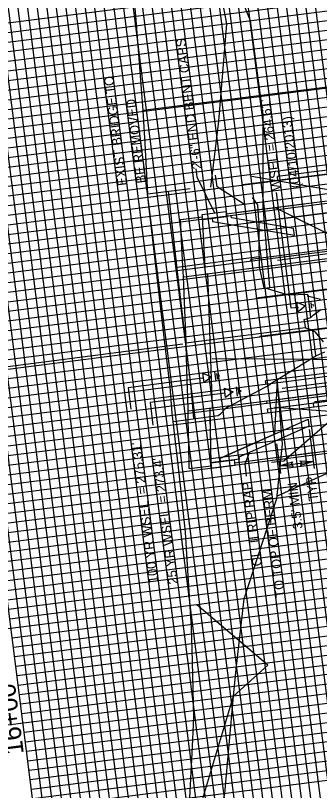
# Model space of a CAD drawing. Extents: x 2166991 to 2168413, y 842679 to 844296.
# Drawn here: x 2167677.7 to 2167837.4, y 843150.5 to 843556.7 of the extents above; entities that cross this region are included whole.
import ezdxf

# ---------------------------------------------------------------- set-up
doc = ezdxf.new("R2010")
doc.units = 0
for name, color, linetype in [('Exist Drainage Structure Bridge Floor', 7, 'Continuous'), ('Exist Horizontal Alignment', 7, 'Continuous'), ('Exist Hydrographic Natural Ground Left', 7, 'Continuous'), ('Exist Hydrographic Natural Ground Right', 7, 'Continuous'), ('Exist Vertical Profile Ground Line', 7, 'Continuous'), ('Old_Level_46', 7, 'Continuous'), ('Prop Drainage Structure Bridge', 7, 'Continuous'), ('Prop Erosion Rip Rap Class II', 7, 'Continuous'), ('Prop Hydrographic Scour Overtopping', 7, 'Continuous'), ('Prop Plan Preparation Drainage Notes Label', 7, 'Continuous'), ('Prop Plan Preparation Excavation Hatching', 7, 'Continuous'), ('Prop Plan Preparation Sheet Bridge Report Limited Study CELL', 7, 'Continuous'), ('Prop Plan Preparation Station Label', 7, 'Continuous'), ('Prop Plan Preparation Stream Water Surface', 7, 'Continuous'), ('Prop Plan Preparation Water Surface Symbol CELL', 7, 'Continuous'), ('Scratch_Level_2', 7, 'Continuous'), ('Scratch_Level_3', 7, 'Continuous'), ('Scratch_Level_4', 7, 'Continuous'), ('Scratch_Level_8', 7, 'Continuous')]:
    doc.layers.add(name, color=color, linetype=linetype)

msp = doc.modelspace()

# ---------------------------------------------------------------- linework, layer by layer
at = {"layer": 'Exist Drainage Structure Bridge Floor'}
for p, q in [((2167747.12, 843463.2), (2167769.41, 843466.04)), ((2167762.53, 843424.84), (2167805.8, 843430.37)), ((2167767.21, 843385.11), (2167830.11, 843393.15)), ((2167760.56, 843343.94), (2167784.24, 843346.96))]:
    msp.add_line(p, q, dxfattribs=at)
for points in [[(2167760.56, 843343.94), (2167760.1, 843348.27), (2167758.9, 843362.01), (2167756.48, 843382.13), (2167751.73, 843422.48), (2167747.12, 843463.2)], [(2167771.47, 843345.33), (2167771.01, 843349.66), (2167769.81, 843363.4), (2167767.4, 843383.52), (2167762.64, 843423.88), (2167758.03, 843464.59)]]:
    msp.add_lwpolyline(points, dxfattribs=at)
at = {"layer": 'Exist Horizontal Alignment'}
for points in [[(2167698.15, 843912.6), (2167700.9, 843897.02), (2167704.98, 843873.76), (2167712.78, 843830.82), (2167715.25, 843815.08), (2167719.44, 843788.58), (2167721.24, 843770.88), (2167724.14, 843742.72), (2167725.44, 843727.75), (2167727.98, 843698.45), (2167729.76, 843678.17), (2167732.36, 843648.31), (2167734.01, 843631.06), (2167736.91, 843601.24), (2167740.82, 843556.48), (2167742.38, 843536.39), (2167744.64, 843506.82), (2167745.73, 843489.59), (2167747.12, 843463.2)], [(2167751.39, 842824.91), (2167752.39, 842844.74), (2167753.95, 842874.72), (2167755.15, 842897.27), (2167757.06, 842927.31), (2167757.92, 842945.41), (2167760.09, 842975.47), (2167761.25, 842993.97), (2167762.76, 843023.98), (2167763.76, 843044.55), (2167765.23, 843074.51), (2167766.29, 843095.78), (2167768.15, 843125.8), (2167769.02, 843139.96), (2167770.48, 843169.95), (2167771.39, 843188.46), (2167770.67, 843218.15), (2167770.25, 843236.07), (2167768.33, 843265.68), (2167767.02, 843285.86), (2167763.97, 843315.19), (2167760.56, 843343.94)]]:
    msp.add_lwpolyline(points, dxfattribs=at)
at = {"layer": 'Exist Hydrographic Natural Ground Left'}
for points in [[(2167811.3, 843414.12), (2167807.83, 843456.76), (2167807.84, 843504.28), (2167801.18, 843553.83), (2167790.23, 843580.86), (2167790.98, 843602.94), (2167784.08, 843652.46), (2167781.01, 843702.48), (2167748.47, 843748.73), (2167729.16, 843847.07), (2167716.86, 843895.91), (2167712.99, 843945.82), (2167712.65, 843970.98), (2167709.18, 843995.74)], [(2167757.79, 842963.56), (2167770.55, 842995.45), (2167773.98, 843046.3), (2167776.61, 843068.3), (2167777.35, 843097.13), (2167787.62, 843148.85), (2167792.18, 843199.84), (2167793.61, 843214.01), (2167797.76, 843250.96), (2167815.06, 843303.58), (2167817.99, 843332.01), (2167815.17, 843366.59)]]:
    msp.add_lwpolyline(points, dxfattribs=at)
at = {"layer": 'Exist Hydrographic Natural Ground Right'}
for points in [[(2167780.31, 843466.62), (2167784.52, 843501.3), (2167788.71, 843552.24), (2167783.57, 843580.01), (2167779.35, 843601.45), (2167769.15, 843650.56), (2167754.8, 843699.13), (2167753.25, 843749.34), (2167741.46, 843798.24), (2167722.31, 843846.2), (2167712.49, 843895.35), (2167692.49, 843943.2), (2167687.3, 843967.74), (2167682.51, 843992.33)], [(2167764.31, 843094.3), (2167776.57, 843147.44), (2167792.18, 843199.84), (2167810.26, 843216.13), (2167772.9, 843247.78)]]:
    msp.add_lwpolyline(points, dxfattribs=at)
at = {"layer": 'Exist Vertical Profile Ground Line'}
for points in [[(2167805.68, 843446.76), (2167804.98, 843457.45), (2167802.15, 843461.2)], [(2167837.93, 843407.87), (2167831.79, 843409.39), (2167831.14, 843410.52), (2167821.21, 843410.07), (2167808.38, 843413.88), (2167805.82, 843424.85), (2167805.79, 843436.55), (2167805.78, 843445.31), (2167805.69, 843446.57)], [(2167839.45, 843385.69), (2167835.28, 843390.74), (2167832.96, 843391.91), (2167830.17, 843392.87), (2167829.29, 843397.37), (2167832.89, 843398.38), (2167834.04, 843399.62), (2167838.15, 843402.55)], [(2167784.24, 843346.96), (2167785.37, 843347.8), (2167788.65, 843351.29), (2167790.08, 843351.91), (2167811.52, 843363.23), (2167811.76, 843363.73), (2167835.45, 843378.32), (2167840.17, 843380.47)]]:
    msp.add_lwpolyline(points, dxfattribs=at)
at = {"layer": 'Old_Level_46'}
for points in [[(2167798.06, 843457.66), (2167783.65, 843466.84), (2167782.87, 843472.96)], [(2167775.92, 843366.58), (2167736.94, 843361.6), (2167738.37, 843350.34)], [(2167787.78, 843358.8), (2167748.42, 843353.78), (2167749.94, 843341.89)]]:
    msp.add_lwpolyline(points, dxfattribs=at)
at = {"layer": 'Prop Drainage Structure Bridge'}
for p, q in [((2167788.33, 843452.77), (2167829.5, 843458.03)), ((2167794.54, 843453.55), (2167848.25, 843460.41)), ((2167775.78, 843452.41), (2167788.18, 843454)), ((2167788.17, 843454), (2167788.52, 843451.28)), ((2167764.37, 843449.7), (2167775.94, 843451.17)), ((2167766.02, 843449.91), (2167775.94, 843451.17)), ((2167776.13, 843449.69), (2167788.53, 843451.27)), ((2167765.91, 843419.65), (2167960.44, 843444.5)), ((2167768.38, 843349.4), (2167969.63, 843375.1)), ((2167821.41, 843325.93), (2167864.73, 843331.46)), ((2167780.32, 843322.19), (2167792.72, 843323.77)), ((2167793.05, 843321.04), (2167792.71, 843323.76)), ((2167792.9, 843322.27), (2167834.07, 843327.53)), ((2167768.96, 843319.23), (2167780.51, 843320.7)), ((2167770.59, 843319.44), (2167780.51, 843320.7)), ((2167780.67, 843319.46), (2167793.07, 843321.05))]:
    msp.add_line(p, q, dxfattribs=at)
for points in [[(2167768.96, 843319.23), (2167768.73, 843332.94), (2167768.63, 843337.97), (2167768.48, 843344.95), (2167768.38, 843349.4), (2167768.21, 843356.31), (2167767.95, 843365.56), (2167767.37, 843383.75), (2167767.32, 843385.13), (2167766.83, 843398.23), (2167765.91, 843419.65), (2167765.64, 843425.24), (2167764.98, 843438.32), (2167764.72, 843443.32), (2167764.37, 843449.7)], [(2167780.51, 843320.7), (2167779.93, 843350.87), (2167781.17, 843351.03), (2167778.7, 843421.28), (2167777.46, 843421.13), (2167775.94, 843451.17)]]:
    msp.add_lwpolyline(points, dxfattribs=at)
at = {"layer": 'Prop Erosion Rip Rap Class II'}
for points in [[(2167781.08, 843450.32), (2167781.28, 843448.75), (2167824.28, 843441.49), (2167823.72, 843445.01), (2167791.15, 843450.59), (2167790.99, 843451.61), (2167788.51, 843451.29)], [(2167785.27, 843322.82), (2167785.06, 843324.39), (2167831.4, 843345.02), (2167831.8, 843341.39), (2167814.14, 843333.63), (2167795.08, 843325.09), (2167795.19, 843324.06), (2167792.71, 843323.75)]]:
    msp.add_lwpolyline(points, close=True, dxfattribs=at)
at = {"layer": 'Prop Hydrographic Scour Overtopping'}
for p, q in [((2167960.44, 843444.56), (2167801.84, 843472.35)), ((2167969.56, 843375.09), (2167815.18, 843304.73)), ((2167814.98, 843365.72), (2167814.45, 843369.88))]:
    msp.add_line(p, q, dxfattribs=at)
at = {"layer": 'Prop Plan Preparation Drainage Notes Label'}
for p, q in [((2167765.56, 843384.32), (2167521.8, 843353.19)), ((2167832.06, 843339.76), (2167834.67, 843319.3)), ((2167814.9, 843332.2), (2167816.89, 843316.6)), ((2167816.37, 843320.64), (2167834.21, 843322.92)), ((2167823.97, 843296.65), (2167823.97, 843296.58))]:
    msp.add_line(p, q, dxfattribs=at)
for points in [[(2167772.38, 843476.34), (2167772.93, 843472.04), (2167782.2, 843453.23)], [(2167814.63, 843463.88), (2167822.41, 843403.37), (2167826.31, 843403.86)], [(2167895.15, 843315.83), (2167893.14, 843331.53), (2167887.44, 843375.99), (2167781.12, 843376.66)], [(2167854.04, 843318.38), (2167850.29, 843348.53), (2167813.82, 843351.12)], [(2167799.13, 843315.18), (2167798.3, 843321.71), (2167800.64, 843327.58)]]:
    msp.add_lwpolyline(points, dxfattribs=at)
for points in [[(2167823.5, 843320.33), (2167816.37, 843320.64), (2167823.23, 843322.78), (2167822.49, 843321.42)], [(2167827.08, 843323.23), (2167834.21, 843322.92), (2167827.35, 843320.79), (2167828.09, 843322.14)]]:
    msp.add_lwpolyline(points, close=True, dxfattribs=at)
at = {"layer": 'Prop Plan Preparation Excavation Hatching'}
for p, q in [((2167776.13, 843449.7), (2167775.78, 843452.43)), ((2167780.32, 843322.17), (2167780.67, 843319.45))]:
    msp.add_line(p, q, dxfattribs=at)
msp.add_lwpolyline([(2167780.51, 843322.21), (2167780.02, 843346.42), (2167784.24, 843346.96), (2167785.37, 843347.8), (2167788.65, 843351.29), (2167790.08, 843351.91), (2167811.52, 843363.23), (2167811.76, 843363.73), (2167815.13, 843365.81), (2167813.8, 843337.17), (2167785.06, 843324.39), (2167785.27, 843322.82), (2167781.42, 843322.33)], close=True, dxfattribs=at)
at = {"layer": 'Prop Plan Preparation Sheet Bridge Report Limited Study CELL'}
for p, q in [((2167933.95, 842789.5), (2167775.57, 844029.42)), ((2167884.35, 842783.16), (2167725.98, 844023.09)), ((2167834.76, 842776.83), (2167676.38, 844016.75)), ((2167785.16, 842770.49), (2167626.78, 844010.42)), ((2167735.56, 842764.16), (2167577.19, 844004.08)), ((2167910.94, 842811.76), (2167758.9, 844002.09)), ((2167915.9, 842812.39), (2167763.86, 844002.72)), ((2167920.86, 842813.03), (2167768.82, 844003.36)), ((2167925.82, 842813.66), (2167773.78, 844003.99)), ((2167886.15, 842808.59), (2167734.11, 843998.92)), ((2167891.11, 842809.23), (2167739.06, 843999.56)), ((2167896.07, 842809.86), (2167744.02, 844000.19)), ((2167901.03, 842810.49), (2167748.98, 844000.82)), ((2167905.98, 842811.13), (2167753.94, 844001.46)), ((2167851.43, 842804.16), (2167699.39, 843994.49)), ((2167856.39, 842804.79), (2167704.35, 843995.12)), ((2167861.35, 842805.43), (2167709.31, 843995.76)), ((2167866.31, 842806.06), (2167714.27, 843996.39)), ((2167871.27, 842806.69), (2167719.23, 843997.02)), ((2167876.23, 842807.33), (2167724.19, 843997.66)), ((2167816.71, 842799.72), (2167664.67, 843990.05)), ((2167821.67, 842800.36), (2167669.63, 843990.69)), ((2167826.63, 842800.99), (2167674.59, 843991.32)), ((2167836.55, 842802.26), (2167684.51, 843992.59)), ((2167841.51, 842802.89), (2167689.47, 843993.22)), ((2167846.47, 842803.53), (2167694.43, 843993.85)), ((2167786.95, 842795.92), (2167634.91, 843986.25)), ((2167791.91, 842796.56), (2167639.87, 843986.89)), ((2167796.87, 842797.19), (2167644.83, 843987.52)), ((2167801.83, 842797.82), (2167649.79, 843988.15)), ((2167806.79, 842798.46), (2167654.75, 843988.79)), ((2167811.75, 842799.09), (2167659.71, 843989.42)), ((2167752.23, 842791.49), (2167600.19, 843981.82)), ((2167757.19, 842792.12), (2167605.15, 843982.45)), ((2167762.15, 842792.76), (2167610.11, 843983.09)), ((2167767.11, 842793.39), (2167615.07, 843983.72)), ((2167772.07, 842794.02), (2167620.03, 843984.35)), ((2167777.03, 842794.66), (2167624.99, 843984.99)), ((2167737.35, 842789.59), (2167585.31, 843979.92)), ((2167742.31, 842790.22), (2167590.27, 843980.55)), ((2167747.27, 842790.86), (2167595.23, 843981.18)), ((2168131.44, 843611.14), (2167635.47, 843547.79)), ((2168132.07, 843606.18), (2167636.1, 843542.83)), ((2168132.71, 843601.22), (2167636.74, 843537.87)), ((2168133.34, 843596.26), (2167612.57, 843529.74)), ((2168133.97, 843591.3), (2167638, 843527.95)), ((2168134.61, 843586.34), (2167638.64, 843522.99)), ((2168135.24, 843581.38), (2167639.27, 843518.03)), ((2168135.87, 843576.42), (2167639.9, 843513.07)), ((2168136.51, 843571.46), (2167640.54, 843508.11)), ((2168137.14, 843566.5), (2167641.17, 843503.15)), ((2168137.77, 843561.54), (2167641.8, 843498.19)), ((2168138.41, 843556.58), (2167642.44, 843493.23)), ((2168139.04, 843551.62), (2167643.07, 843488.27)), ((2168139.68, 843546.66), (2167618.91, 843480.15)), ((2168140.31, 843541.7), (2167644.34, 843478.35)), ((2168140.94, 843536.74), (2167644.97, 843473.39)), ((2168141.58, 843531.78), (2167645.61, 843468.43)), ((2168142.21, 843526.83), (2167646.24, 843463.47)), ((2168142.84, 843521.87), (2167646.87, 843458.52)), ((2168143.48, 843516.91), (2167647.51, 843453.56)), ((2168144.11, 843511.95), (2167648.14, 843448.6)), ((2168144.74, 843506.99), (2167648.77, 843443.64)), ((2168145.38, 843502.03), (2167649.41, 843438.68)), ((2168146.01, 843497.07), (2167625.24, 843430.55)), ((2168146.64, 843492.11), (2167650.67, 843428.76)), ((2168147.28, 843487.15), (2167651.31, 843423.8)), ((2168147.91, 843482.19), (2167651.94, 843418.84)), ((2168148.54, 843477.23), (2167652.57, 843413.88)), ((2168149.18, 843472.27), (2167653.21, 843408.92)), ((2168149.81, 843467.31), (2167653.84, 843403.96)), ((2168150.44, 843462.35), (2167654.47, 843399)), ((2168151.08, 843457.39), (2167655.11, 843394.04)), ((2168151.71, 843452.43), (2167655.74, 843389.08)), ((2168152.35, 843447.47), (2167631.58, 843380.95)), ((2168152.98, 843442.51), (2167657.01, 843379.16)), ((2168153.61, 843437.55), (2167657.64, 843374.2)), ((2168154.25, 843432.59), (2167658.28, 843369.24)), ((2168154.88, 843427.63), (2167658.91, 843364.28)), ((2168155.51, 843422.67), (2167659.54, 843359.32)), ((2168156.15, 843417.71), (2167660.18, 843354.36)), ((2168156.78, 843412.75), (2167660.81, 843349.4)), ((2168157.41, 843407.79), (2167661.44, 843344.44)), ((2168158.05, 843402.83), (2167662.08, 843339.48)), ((2168158.68, 843397.87), (2167637.91, 843331.35)), ((2168159.31, 843392.91), (2167663.34, 843329.56)), ((2168159.95, 843387.95), (2167663.98, 843324.6)), ((2168160.58, 843382.99), (2167664.61, 843319.64)), ((2168161.21, 843378.03), (2167665.24, 843314.68)), ((2168161.85, 843373.07), (2167665.88, 843309.72)), ((2168162.48, 843368.11), (2167666.51, 843304.76)), ((2168163.11, 843363.15), (2167667.14, 843299.8)), ((2168163.75, 843358.2), (2167667.78, 843294.84)), ((2168164.38, 843353.24), (2167668.41, 843289.89)), ((2168165.02, 843348.28), (2167644.25, 843281.76)), ((2168165.65, 843343.32), (2167669.68, 843279.97)), ((2168166.28, 843338.36), (2167670.31, 843275.01)), ((2168166.92, 843333.4), (2167670.95, 843270.05)), ((2168167.55, 843328.44), (2167671.58, 843265.09)), ((2168168.18, 843323.48), (2167672.21, 843260.13)), ((2168168.82, 843318.52), (2167672.85, 843255.17)), ((2168169.45, 843313.56), (2167673.48, 843250.21)), ((2168170.08, 843308.6), (2167674.11, 843245.25)), ((2168170.72, 843303.64), (2167674.75, 843240.29)), ((2168171.35, 843298.68), (2167650.58, 843232.16)), ((2168171.98, 843293.72), (2167676.01, 843230.37)), ((2168172.62, 843288.76), (2167676.65, 843225.41)), ((2168173.25, 843283.8), (2167677.28, 843220.45)), ((2168173.88, 843278.84), (2167677.91, 843215.49)), ((2168174.52, 843273.88), (2167678.55, 843210.53)), ((2168175.15, 843268.92), (2167679.18, 843205.57)), ((2168175.78, 843263.96), (2167679.81, 843200.61)), ((2168176.42, 843259), (2167680.45, 843195.65)), ((2168177.05, 843254.04), (2167681.08, 843190.69)), ((2168177.69, 843249.08), (2167656.92, 843182.56)), ((2168178.32, 843244.12), (2167682.35, 843180.77)), ((2168178.95, 843239.16), (2167682.98, 843175.81)), ((2168179.59, 843234.2), (2167683.62, 843170.85)), ((2168180.22, 843229.24), (2167684.25, 843165.89)), ((2168180.85, 843224.28), (2167684.88, 843160.93)), ((2168181.49, 843219.32), (2167685.52, 843155.97)), ((2168182.12, 843214.36), (2167686.15, 843151.01)), ((2168182.75, 843209.4), (2167686.78, 843146.05)), ((2168183.39, 843204.44), (2167687.42, 843141.09)), ((2168184.02, 843199.48), (2167663.25, 843132.97))]:
    msp.add_line(p, q, dxfattribs=at)
at = {"layer": 'Prop Plan Preparation Stream Water Surface'}
for p, q in [((2167832.93, 843398.43), (2167831.46, 843409.95)), ((2167835.48, 843378.51), (2167833.82, 843391.48))]:
    msp.add_line(p, q, dxfattribs=at)
at = {"layer": 'Prop Plan Preparation Water Surface Symbol CELL'}
for p, q in [((2167832.46, 843402.13), (2167831.83, 843407.09)), ((2167833.33, 843403.25), (2167832.95, 843406.22)), ((2167834.19, 843404.36), (2167834.07, 843405.36)), ((2167783.07, 843365.02), (2167782.43, 843369.98)), ((2167783.93, 843366.14), (2167783.55, 843369.11)), ((2167784.8, 843367.25), (2167784.67, 843368.25)), ((2167794.41, 843357.13), (2167793.77, 843362.09)), ((2167795.27, 843358.25), (2167794.89, 843361.22)), ((2167796.14, 843359.36), (2167796.01, 843360.36))]:
    msp.add_line(p, q, dxfattribs=at)
for points in [[(2167826.14, 843401.4), (2167825.51, 843406.36), (2167830.13, 843404.43)], [(2167776.75, 843364.29), (2167776.11, 843369.25), (2167780.73, 843367.32)], [(2167788.09, 843356.4), (2167787.45, 843361.35), (2167792.07, 843359.42)]]:
    msp.add_lwpolyline(points, close=True, dxfattribs=at)
at = {"layer": 'Scratch_Level_2'}
for p, q in [((2168101.65, 843552.42), (2167744.64, 843506.82)), ((2167742.39, 843536.24), (2167742.38, 843536.39)), ((2167744.71, 843506.3), (2167744.64, 843506.82))]:
    msp.add_line(p, q, dxfattribs=at)
at = {"layer": 'Scratch_Level_3'}
for p, q in [((2167815.39, 843428.51), (2168411.81, 843504.69)), ((2167858.33, 843434), (2167813.96, 843456.03)), ((2167817.84, 843361.31), (2168278.64, 843420.17)), ((2167870.26, 843368), (2167818.59, 843323.14)), ((2167818.59, 843323.14), (2167812.28, 843322.33))]:
    msp.add_line(p, q, dxfattribs=at)
at = {"layer": 'Scratch_Level_4'}
for p, q in [((2168088.64, 843507.14), (2167815.29, 843472.22)), ((2167815.58, 843469.98), (2167815.29, 843472.22)), ((2168083.95, 843385.46), (2167834.18, 843353.55)), ((2168082.98, 843385.82), (2167834.96, 843354.14)), ((2167834.45, 843351.42), (2167834.18, 843353.55)), ((2167835.02, 843353.66), (2167834.96, 843354.14))]:
    msp.add_line(p, q, dxfattribs=at)
at = {"layer": 'Scratch_Level_8'}
for p, q in [((2168091.54, 843505.51), (2167796.91, 843467.87)), ((2168090.16, 843485.03), (2167799.4, 843447.89)), ((2167796.94, 843467.6), (2167796.91, 843467.87)), ((2168089.2, 843465.59), (2167801.33, 843428.82)), ((2167799.41, 843447.76), (2167799.4, 843447.89)), ((2168087.87, 843444.75), (2167804.17, 843408.52)), ((2167801.45, 843427.85), (2167801.33, 843428.82)), ((2168086.81, 843424.32), (2167806.08, 843388.46)), ((2167804.23, 843408.05), (2167804.17, 843408.52)), ((2168086.26, 843403.82), (2167808.5, 843368.34)), ((2168086.42, 843400.54), (2167809.11, 843365.12)), ((2168085.19, 843389.79), (2167809.7, 843354.6)), ((2167806.12, 843388.13), (2167806.08, 843388.46)), ((2168085.19, 843385.4), (2167810.15, 843350.27)), ((2167808.51, 843368.27), (2167808.5, 843368.34)), ((2167809.34, 843363.33), (2167809.11, 843365.12)), ((2167809.86, 843353.32), (2167809.7, 843354.6)), ((2167810.4, 843348.35), (2167810.15, 843350.27))]:
    msp.add_line(p, q, dxfattribs=at)

# ---------------------------------------------------------------- texts
at = {"layer": 'Old_Level_46'}
for s, p in [('EXIST BRIDGE TO', (2167736.43, 843467.74)), ('BE REMOVED', (2167746.35, 843469.01)), ("100 YR WSEL  = 275.31'", (2167752.81, 843259.57)), ("25 YR WSEL  = 273.4'", (2167763.11, 843258.81))]:
    msp.add_text(s, height=5, rotation=97.279, dxfattribs=at).set_placement(p)
at = {"layer": 'Prop Plan Preparation Drainage Notes Label'}
for s, p in [('2\'-6" END BENT CAPS', (2167775.63, 843476.4)), ("WSEL = 264.61'", (2167817.32, 843465.21)), ('(04/10/2013)', (2167827.24, 843466.48)), ('CL. II RIP RAP', (2167807.28, 843268.29)), ("3.5' MIN", (2167828.62, 843287.77)), ('TYP', (2167836.81, 843302.55)), ('TO TOP OF BERM', (2167819.45, 843251.91))]:
    msp.add_text(s, height=5, rotation=97.279, dxfattribs=at).set_placement(p)
at = {"layer": 'Prop Plan Preparation Station Label'}
msp.add_text('16+00', height=10, rotation=97.279, dxfattribs=at).set_placement((2167682.16, 843169.8))

doc.saveas('drawing.dxf')
